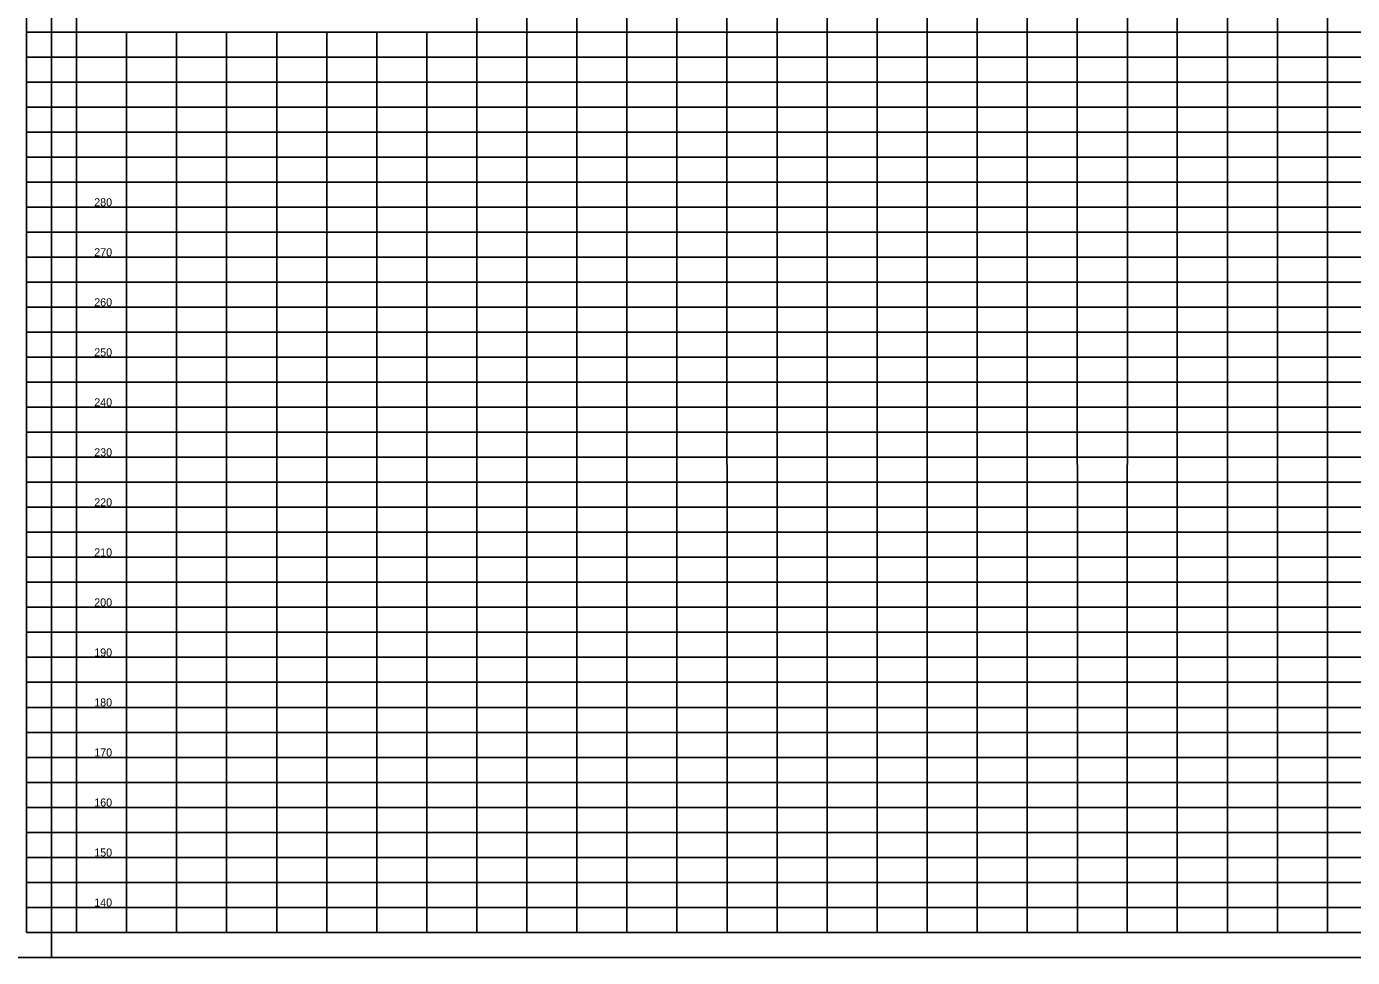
# Model space of a CAD drawing. Extents: x 1870112 to 1888282, y 758439 to 777406.
# Drawn here: x 1882932 to 1884257, y 758439 to 759370 of the extents above; entities that cross this region are included whole.
import ezdxf

# ---------------------------------------------------------------- set-up
doc = ezdxf.new("R2010")
doc.units = 0
for name, color, linetype in [('RD_DDB_ElevTX', 7, 'Continuous'), ('RD_PD_WallFill', 7, 'Continuous'), ('RD_SHT_IplotShp', 7, 'Continuous')]:
    doc.layers.add(name, color=color, linetype=linetype)

msp = doc.modelspace()

# ---------------------------------------------------------------- linework, layer by layer
at = {"layer": 'RD_PD_WallFill'}
for p, q in [((1882931.6, 758464.2), (1882931.6, 759514.2)), ((1882981.6, 758464.2), (1882981.6, 759514.2)), ((1882981.6, 758464.2), (1882981.6, 759514.2)), ((1883381.6, 758464.2), (1883381.6, 759514.2)), ((1883381.6, 758464.2), (1883381.6, 759514.2)), ((1883431.6, 758464.2), (1883431.6, 759514.2)), ((1883431.6, 758464.2), (1883431.6, 759514.2)), ((1883481.6, 758464.2), (1883481.6, 759514.2)), ((1883481.6, 758464.2), (1883481.6, 759514.2)), ((1883531.6, 758464.2), (1883531.6, 759514.2)), ((1883531.6, 758464.2), (1883531.6, 759514.2)), ((1883581.6, 758464.2), (1883581.6, 759514.2)), ((1883581.6, 758464.2), (1883581.6, 759514.2)), ((1883631.7, 758464.2), (1883631.6, 759514.2)), ((1883631.7, 758464.2), (1883631.6, 759514.2)), ((1883681.6, 758464.2), (1883681.7, 759514.2)), ((1883681.6, 758464.2), (1883681.7, 759514.2)), ((1883731.6, 758464.2), (1883731.6, 759514.2)), ((1883731.6, 758464.2), (1883731.6, 759514.2)), ((1883781.6, 758464.2), (1883781.6, 759514.2)), ((1883781.6, 758464.2), (1883781.6, 759514.2)), ((1883831.6, 758464.2), (1883831.6, 759514.2)), ((1883831.6, 758464.2), (1883831.6, 759514.2)), ((1883881.6, 758464.2), (1883881.6, 759514.2)), ((1883881.6, 758464.2), (1883881.6, 759514.2)), ((1883931.6, 758464.2), (1883931.6, 759514.2)), ((1883931.6, 758464.2), (1883931.6, 759514.2)), ((1883981.7, 758464.2), (1883981.6, 759514.2)), ((1883981.7, 758464.2), (1883981.6, 759514.2)), ((1884031.6, 758464.2), (1884031.7, 759514.2)), ((1884031.6, 758464.2), (1884031.7, 759514.2)), ((1884081.6, 758464.2), (1884081.6, 759514.2)), ((1884081.6, 758464.2), (1884081.6, 759514.2)), ((1884131.6, 758464.2), (1884131.6, 759514.2)), ((1884131.6, 758464.2), (1884131.6, 759514.2)), ((1884181.7, 758464.2), (1884181.6, 759514.2)), ((1884181.7, 758464.2), (1884181.6, 759514.2)), ((1884231.7, 758464.2), (1884231.6, 759514.2)), ((1884231.7, 758464.2), (1884231.6, 759514.2)), ((1882931.6, 759364.2), (1888281.6, 759364.2)), ((1883031.6, 758464.2), (1883031.6, 759364.2)), ((1883031.6, 758464.2), (1883031.6, 759364.2)), ((1883081.6, 758464.2), (1883081.6, 759364.2)), ((1883081.6, 758464.2), (1883081.6, 759364.2)), ((1883131.6, 758464.2), (1883131.6, 759364.2)), ((1883131.6, 758464.2), (1883131.6, 759364.2)), ((1883181.6, 758464.2), (1883181.6, 759364.2)), ((1883181.6, 758464.2), (1883181.6, 759364.2)), ((1883231.6, 758464.2), (1883231.6, 759364.2)), ((1883231.6, 758464.2), (1883231.6, 759364.2)), ((1883281.6, 758464.2), (1883281.6, 759364.2)), ((1883281.6, 758464.2), (1883281.6, 759364.2)), ((1883331.6, 758464.2), (1883331.6, 759364.2)), ((1883331.6, 758464.2), (1883331.6, 759364.2)), ((1882931.6, 759339.2), (1888281.6, 759339.2)), ((1882931.6, 759314.2), (1888281.6, 759314.2)), ((1882931.6, 759289.2), (1888281.6, 759289.2)), ((1882931.6, 759264.2), (1888281.6, 759264.2)), ((1882931.6, 759239.2), (1888281.6, 759239.2)), ((1882931.6, 759214.2), (1888281.6, 759214.2)), ((1882931.6, 759189.2), (1888281.6, 759189.2)), ((1882931.6, 759164.2), (1888281.6, 759164.2)), ((1882931.6, 759139.2), (1888281.6, 759139.2)), ((1882931.6, 759114.2), (1888281.6, 759114.2)), ((1882931.6, 759089.2), (1888281.6, 759089.2)), ((1882931.6, 759064.2), (1888281.6, 759064.2)), ((1882931.6, 759039.2), (1888281.6, 759039.2)), ((1882931.6, 759014.2), (1888281.6, 759014.2)), ((1882931.6, 758989.2), (1888281.6, 758989.2)), ((1882931.6, 758964.2), (1888281.6, 758964.2)), ((1882931.6, 758939.2), (1888281.6, 758939.2)), ((1882931.6, 758914.2), (1888281.6, 758914.2)), ((1882931.6, 758889.2), (1888281.6, 758889.2)), ((1882931.6, 758864.2), (1888281.6, 758864.2)), ((1882931.6, 758839.2), (1888281.6, 758839.2)), ((1882931.6, 758814.2), (1888281.6, 758814.2)), ((1882931.6, 758789.2), (1888281.6, 758789.2)), ((1882931.6, 758764.2), (1888281.6, 758764.2)), ((1882931.6, 758739.2), (1888281.6, 758739.2)), ((1882931.6, 758714.2), (1888281.6, 758714.2)), ((1882931.6, 758689.2), (1888281.6, 758689.2)), ((1882931.6, 758664.2), (1888281.6, 758664.2)), ((1882931.6, 758639.2), (1888281.6, 758639.2)), ((1882931.6, 758614.2), (1888281.6, 758614.2)), ((1882931.6, 758589.2), (1888281.6, 758589.2)), ((1882931.6, 758564.2), (1888281.6, 758564.2)), ((1882931.6, 758539.2), (1888281.6, 758539.2)), ((1882931.6, 758514.2), (1888281.6, 758514.2)), ((1882931.6, 758489.2), (1888281.6, 758489.2)), ((1882931.6, 758464.2), (1888281.6, 758464.2)), ((1882931.6, 758464.2), (1888281.6, 758464.2))]:
    msp.add_line(p, q, dxfattribs=at)
msp.add_lwpolyline([(1882981.6, 759514.2), (1883381.6, 759514.2), (1883381.6, 759364.2), (1882981.6, 759364.2)], close=True, dxfattribs=at)
msp.add_lwpolyline([(1882981.6, 759514.2), (1883381.6, 759514.2), (1883381.6, 759364.2), (1882981.6, 759364.2)], close=True, dxfattribs=at)
msp.add_lwpolyline([(1882981.6, 759514.2), (1883381.6, 759514.2), (1883381.6, 759364.2), (1882981.6, 759364.2)], close=True, dxfattribs=at)
msp.add_lwpolyline([(1882981.6, 759514.2), (1883381.6, 759514.2), (1883381.6, 759364.2), (1882981.6, 759364.2)], close=True, dxfattribs=at)
at = {"layer": 'RD_SHT_IplotShp'}
for points in [[(1877556.6, 758439.1), (1882956.6, 758439.1), (1882956.6, 759539.1), (1877556.6, 759539.1)], [(1882906.6, 758439.2), (1884656.6, 758439.2), (1884656.6, 759539.2), (1882906.6, 759539.2)]]:
    msp.add_lwpolyline(points, close=True, dxfattribs=at)

# ---------------------------------------------------------------- texts
at = {"layer": 'RD_DDB_ElevTX'}
for s, p in [('280', (1882999.3, 759190.1)), ('270', (1882999.3, 759140.1)), ('260', (1882999.3, 759090.1)), ('250', (1882999.3, 759040.1)), ('240', (1882999.3, 758990.1)), ('230', (1882999.3, 758940.1)), ('220', (1882999.3, 758890.1)), ('210', (1882999.3, 758840.1)), ('200', (1882999.3, 758790.1)), ('190', (1882999.3, 758740.1)), ('180', (1882999.3, 758690.1)), ('170', (1882999.3, 758640.1)), ('160', (1882999.3, 758590.1)), ('150', (1882999.3, 758540.1)), ('140', (1882999.3, 758490.1))]:
    msp.add_text(s, height=8, dxfattribs=at).set_placement(p)

doc.saveas('drawing.dxf')
